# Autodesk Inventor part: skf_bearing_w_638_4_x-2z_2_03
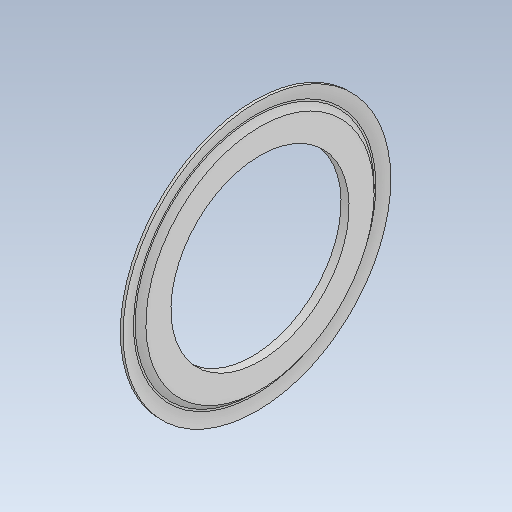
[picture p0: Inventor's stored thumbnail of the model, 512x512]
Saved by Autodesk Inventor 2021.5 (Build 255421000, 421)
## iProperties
Created: 2023-12
Part Number: skf_bearing_w_638_4_x-2z_2_03
Checked By: TraceParts S.A.
Material: Generic
Catalog Web Link: www.traceparts.com
Document SubType Name: Modeling
Designer: TraceParts
Density: 1 g/cm^3
Appearance: Default
Company: TraceParts S.A.
Author: TraceParts
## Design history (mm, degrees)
feature "skf_bearing_w_638_4_x-2z_2_03.ipt"
body "Solid1"
